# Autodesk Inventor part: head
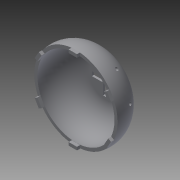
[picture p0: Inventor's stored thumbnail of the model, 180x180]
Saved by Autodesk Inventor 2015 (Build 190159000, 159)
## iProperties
Created: 2017-06
Part Number: head
Material: Generic
Document SubType Name: Modeling
Designer: mcalderon
Density: 1 g/cm^3
Appearance: Default
Author: mcalderon
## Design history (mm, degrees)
sketch "Sketch1"
  geometry: L1 (37, 0)-(40, 0); L2 (0, 28)-(0, 30); L3 (0, 30)-(15, 30); L4 (0, 28)-(15, 28); L5 (0, -0.402)-(0, 35.439); A1 r 25.417 centre (15, 4.583) between (40, 0) and (15, 30); A2 r 22.643 centre (15, 5.357) between (37, 0) and (15, 28); 1 further point
  constraints: 10 end point, 4 point on circle, 3 horizontal, 2 centre point, 2 tangent, 2 vertical
  dimensions: "d4" = 40 distance of point (0, 0) L1.end; "d5" = 30 distance of point (0, 0) L2.end; "d6" = 15 distance of L2.end L3.end; "d7" = 2 distance between parallel lines of L4 L3; "d25" = 15 distance of L4.end L2.start
revolve "Revolution1" sketch "Sketch1" stored, may be unused: angle "d8" = 90 deg
sketch "Sketch2"
  geometry: L1 (0, 37)-(0, 40); L2 (-4, 40)-(4, 40); L3 (4, 40)-(4, 37); L4 (4, 37)-(-4, 37); L5 (-4, 37)-(-4, 40); L6 (-4, 40)-(4, 37); L7 (4, 40)-(-4, 37); L8 (-32.043, 18.5)-(-34.641, 20); L9 (-36.641, 16.536)-(-32.641, 23.464); L10 (-32.641, 23.464)-(-30.043, 21.964); L11 (-30.043, 21.964)-(-34.043, 15.036); L12 (-34.043, 15.036)-(-36.641, 16.536); L13 (-36.641, 16.536)-(-30.043, 21.964); L14 (-32.641, 23.464)-(-34.043, 15.036); L15 (-32.043, -18.5)-(-34.641, -20); L16 (-32.641, -23.464)-(-36.641, -16.536); L17 (-36.641, -16.536)-(-34.043, -15.036); L18 (-34.043, -15.036)-(-30.043, -21.964); L19 (-30.043, -21.964)-(-32.641, -23.464); L20 (-32.641, -23.464)-(-34.043, -15.036); L21 (-36.641, -16.536)-(-30.043, -21.964); L22 (0, -37)-(0, -40); L23 (4, -40)-(-4, -40); L24 (-4, -40)-(-4, -37); L25 (-4, -37)-(4, -37); L26 (4, -37)-(4, -40); L27 (4, -40)-(-4, -37); L28 (-4, -40)-(4, -37); L29 (32.043, -18.5)-(34.641, -20); L30 (36.641, -16.536)-(32.641, -23.464); L31 (32.641, -23.464)-(30.043, -21.964); L32 (30.043, -21.964)-(34.043, -15.036); L33 (34.043, -15.036)-(36.641, -16.536); L34 (36.641, -16.536)-(30.043, -21.964); L35 (32.641, -23.464)-(34.043, -15.036); L36 (32.043, 18.5)-(34.641, 20); L37 (32.641, 23.464)-(36.641, 16.536); L38 (36.641, 16.536)-(34.043, 15.036); L39 (34.043, 15.036)-(30.043, 21.964); L40 (30.043, 21.964)-(32.641, 23.464); L41 (32.641, 23.464)-(34.043, 15.036); L42 (36.641, 16.536)-(30.043, 21.964); 9 further points
  constraints: 84 end point, 13 midpoint, 2 parallel, 2 vertical alignment, 1 horizontal, 1 perpendicular, 87 other
  dimensions: "d32" = 360 deg dimension on point (0, 0) L1.start (derived)
extrude "Extrusion1" join sketch "Sketch2" distance "d15" = 3; taper "d16" = 0 deg
sketch "Sketch3"
  geometry: L1 (25.333, 0)-(-25.333, 0); L2 (0, 21.333)-(0, -25.333); L3 (2.667, 2)-(12.667, 2); L4 (12.667, 2)-(12.667, -2); L5 (12.667, -2)-(2.667, -2); L6 (2.667, -2)-(2.667, 2); L7 (2.667, 2)-(12.667, -2); L8 (12.667, 2)-(2.667, -2); L9 (-21.333, 0)-(25.333, 0); L10 (-2, 2.667)-(-2, 12.667); L11 (2, 2.667)-(-2, 2.667); L12 (2, 12.667)-(2, 2.667); L13 (-2, 12.667)-(2, 12.667); L14 (0, -21.333)-(0, 25.333); L15 (-2.667, -2)-(-12.667, -2); L16 (-2.667, 2)-(-2.667, -2); L17 (-12.667, 2)-(-2.667, 2); L18 (-12.667, -2)-(-12.667, 2); L19 (21.333, 0)-(-25.333, 0); L20 (2, -2.667)-(2, -12.667); L21 (-2, -2.667)-(2, -2.667); L22 (-2, -12.667)-(-2, -2.667); L23 (2, -12.667)-(-2, -12.667); 2 further points
  constraints: 46 end point, 2 horizontal, 2 midpoint, 2 parallel, 1 perpendicular, 1 point on line, 1 vertical, 45 other
  dimensions: "d17" = 4 distance between parallel lines of L5 L3; "d20" = 360 deg dimension on point (0, 0) L2.start (derived); "d24" = 10 distance between parallel lines of L4 L6
extrude "Extrusion2" cut sketch "Sketch3" distance "d22" = 3; taper "d23" = 0 deg
workplane "Work Plane1"
sketch "Sketch4"
  geometry: L1 (0, 32)-(0, -3); L2 (4, -3)-(-4, -3) reference; L3 (-61, 14.5)-(61, 14.5); C1 r 1.5 at (0, 14.5); C2 r 1.5 at (13, 14.5); C3 r 1.5 at (-13, 14.5); C4 r 1.5 at (0, 14.5); 1 further point
  constraints: 4 centre point, 4 end point, 3 horizontal, 2 midpoint, 6 other
  dimensions: "d34" = 3 diameter of C1; "d37" = 13 distance of C1.centre C2.centre; "d40" = 13 distance of C1.centre C3.centre
extrude "Extrusion3" cut sketch "Sketch4" distance "d43" = 10; taper "d44" = 0 deg
body "Solid1"
